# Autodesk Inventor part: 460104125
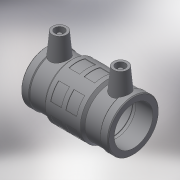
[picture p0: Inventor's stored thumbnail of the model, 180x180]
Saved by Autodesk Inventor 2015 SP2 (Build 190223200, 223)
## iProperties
Created: 2017-06
Part Number: 460104125
Material: Generic
Description: PLASSON LIGHTFIT COUPLER 125
Document SubType Name: Modeling
Designer: KIM
Mass: 89.5427 g
Surface Area: 304.58 cm^2
Volume: 89.5427 cm^3
Density: 1 g/cm^3
Appearance: Default
Author: KIM
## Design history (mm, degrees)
derived "460104.ipt"
feature "Solid1::460104.ipt"
tag "TaggingFeature1"
body "Solid1"
other parameters: "d13" = 173, "d14" = 17.6296, "d15" = 85, "d16" = 85, "d17" = 123.75, "d18" = 125, "d19" = 3.52592, "d20" = 168 deg, "d22" = 140.06, "d23" = 149, "d24" = 135.8582, "d25" = 135 deg, "d26" = 69.2, "d27" = 135 deg, "d29" = 87, "d35" = 15, "d39" = 5 deg, "d44" = 4, "d46" = 14, "d47" = 0, "d52" = 146.02, "d53" = 8.65, "d54" = 8.65, "d55" = 8.65, "d56" = 35 deg, "d58" = 360 deg, "d60" = 17, "d61" = 135 deg, "d62" = 72.66, "d63" = 3, "d64" = 0, "d_" = 125, "L_" = 173, "L_1" = 85, "D_" = 149, "A_" = 87, "d_2" = 12
